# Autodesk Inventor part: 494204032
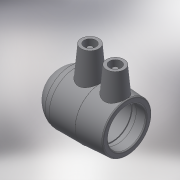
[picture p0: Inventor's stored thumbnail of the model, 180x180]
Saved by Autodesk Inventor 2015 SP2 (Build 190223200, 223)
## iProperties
Created: 2017-06
Part Number: 494204032
Material: Generic
Description: PLASSON END CAP MONOLITHIC 32
Document SubType Name: Modeling
Designer: Кирилл
Density: 1 g/cm^3
Appearance: Default
Author: Кирилл
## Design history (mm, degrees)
derived "494204.ipt"
feature "Solid1::494204.ipt"
tag "TaggingFeature1"
body "Solid1"
other parameters: "d0" = 63, "d1" = 1, "d2" = 44, "d3" = 32, "d4" = 44, "d5" = 6.3, "d7" = 1.32, "d8" = 22.05, "d10" = 0.88, "d11" = 12.6, "d12" = 168 deg, "d13" = 4.2, "d14" = 32, "d15" = 46, "d16" = 15, "d17" = 31.5, "d18" = 1, "d20" = 5 deg, "d21" = 41.4, "d22" = 15, "d23" = 1, "d24" = 52.92, "d26" = 5 deg, "d27" = 4, "d29" = 14, "d30" = 0, "d31" = 4, "d33" = 14, "d34" = 0, "d37" = 28.8, "d38" = 44, "d39" = 50.6, "d40" = 35.2, "d41" = 1.6, "d42" = 0, "d44" = 360 deg, "d46" = 3, "d47" = 0, "d48" = 3, "d49" = 0, "d_" = 32, "L_" = 63, "L_1" = 44, "D_" = 44, "A_" = 46, "d_2" = 12
